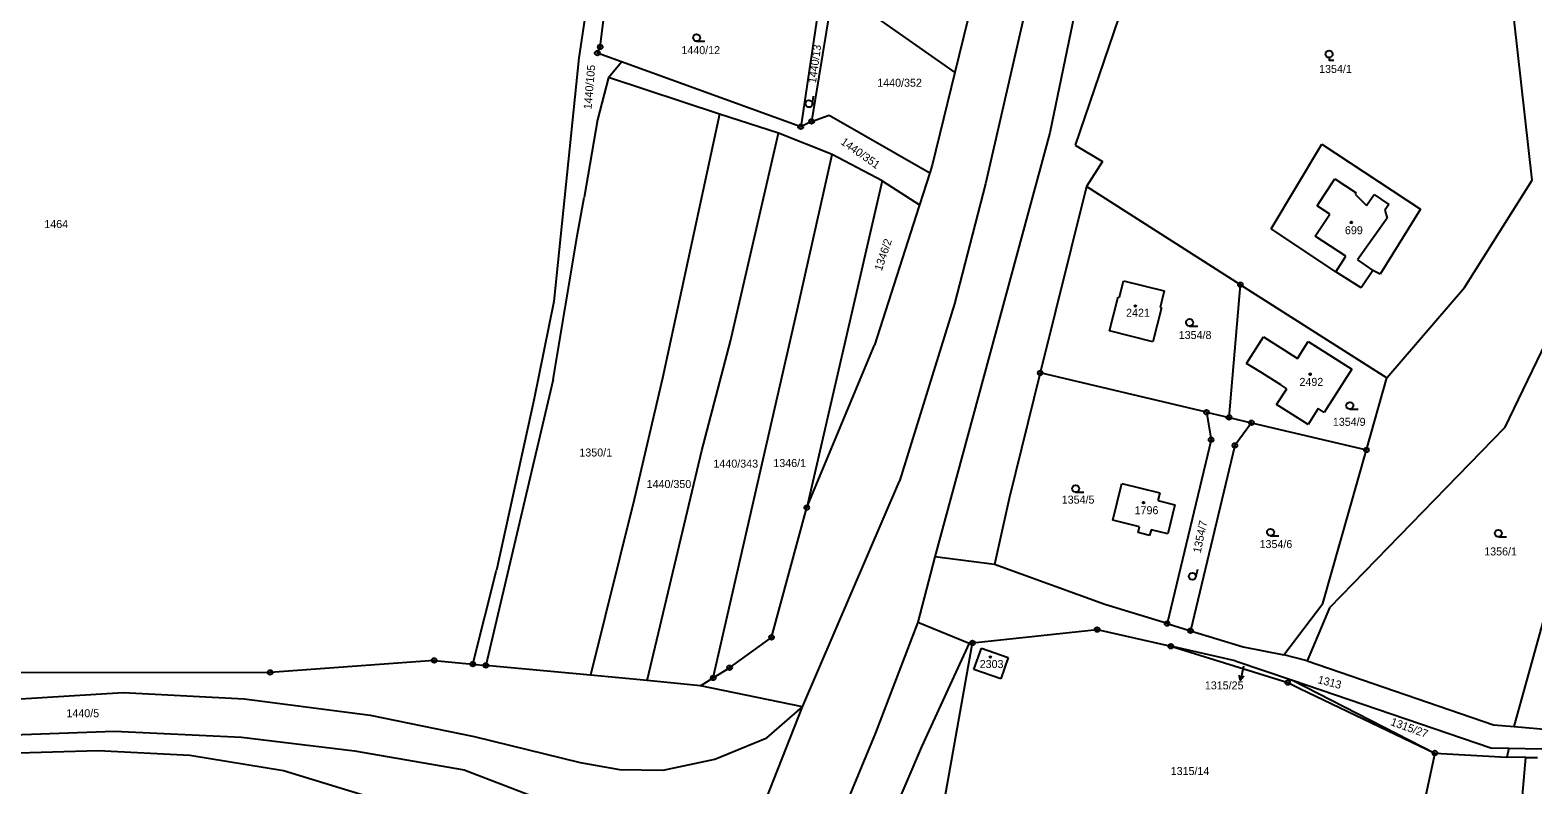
# Model space of a CAD drawing. Extents: x -779596 to -776743, y -1030330 to -1024513.
# Drawn here: x -778848.9 to -778529.6, y -1029527.2 to -1029366.8 of the extents above; entities that cross this region are included whole.
import ezdxf

# ---------------------------------------------------------------- set-up
doc = ezdxf.new("R2010")
doc.units = 0
for name, color, linetype in [('hranice parcel', 7, 'Continuous'), ('hranice vnitřní', 7, 'Continuous'), ('kultura', 7, 'Continuous'), ('Kód', 7, 'Continuous'), ('č_ parcel šipka', 7, 'Continuous'), ('č_pacel stav_', 7, 'Continuous'), ('č_parcel poz_', 7, 'Continuous')]:
    doc.layers.add(name, color=color, linetype=linetype)

msp = doc.modelspace()

# ---------------------------------------------------------------- linework, layer by layer
at = {"layer": 'hranice parcel'}
for points in [[(-778727.78, -1029370.36), (-778723.25, -1029334.33)], [(-778608.5, -1029337.19), (-778626.9, -1029391.19)], [(-778727.76, -1029341.91), (-778732.32, -1029372.68)], [(-778680.37, -1029354.91), (-778685.2, -1029387.32)], [(-778678.25, -1029357.68), (-778682.87, -1029386.19)], [(-778678.25, -1029357.68), (-778652.43, -1029375.78)], [(-778647.89, -1029357.22), (-778652.43, -1029375.78)], [(-778529.81, -1029398.69), (-778534.38, -1029357.58)], [(-778728.4, -1029371.67), (-778727.78, -1029370.36)], [(-778723.3, -1029373.52), (-778728.4, -1029371.67)], [(-778732.32, -1029372.68), (-778737.68, -1029424.44)], [(-778726, -1029376.83), (-778723.3, -1029373.52)], [(-778685.2, -1029387.32), (-778723.3, -1029373.52)], [(-778726, -1029376.83), (-778728.4, -1029385.86)], [(-778702.44, -1029384.63), (-778726, -1029376.83)], [(-778652.43, -1029375.78), (-778657.26, -1029395.5)], [(-778702.44, -1029384.63), (-778714.58, -1029440.73)], [(-778689.9, -1029388.68), (-778702.44, -1029384.63)], [(-778728.4, -1029385.86), (-778731.19, -1029402.33)], [(-778682.87, -1029386.19), (-778685.2, -1029387.32)], [(-778682.87, -1029386.19), (-778679.12, -1029384.87)], [(-778679.12, -1029384.87), (-778657.76, -1029397.08)], [(-778700.09, -1029432.9), (-778689.9, -1029388.68)], [(-778678.49, -1029393.24), (-778689.9, -1029388.68)], [(-778585.21, -1029409), (-778574.45, -1029391.04)], [(-778574.45, -1029391.04), (-778553.51, -1029404.79)], [(-778685.92, -1029426.38), (-778678.49, -1029393.24)], [(-778667.86, -1029398.83), (-778678.49, -1029393.24)], [(-778626.9, -1029391.19), (-778621.06, -1029394.71)], [(-778657.76, -1029397.08), (-778659.95, -1029403.89)], [(-778657.26, -1029395.5), (-778657.76, -1029397.08)], [(-778621.06, -1029394.71), (-778624.5, -1029400.03)], [(-778667.86, -1029398.83), (-778683.91, -1029468.24)], [(-778667.86, -1029398.83), (-778659.95, -1029403.89)], [(-778624.5, -1029400.03), (-778634.29, -1029439.63)], [(-778591.79, -1029420.88), (-778624.5, -1029400.03)], [(-778544.15, -1029421.45), (-778529.81, -1029398.69)], [(-778732.65, -1029410.17), (-778731.19, -1029402.33)], [(-778660.1, -1029404.35), (-778669.53, -1029433.74)], [(-778659.95, -1029403.89), (-778660.1, -1029404.35)], [(-778553.51, -1029404.79), (-778562.1, -1029418.66)], [(-778737.78, -1029441.03), (-778732.65, -1029410.17)], [(-778571.54, -1029418.12), (-778585.21, -1029409)], [(-778566.15, -1029421.57), (-778571.54, -1029418.12)], [(-778563.62, -1029417.83), (-778566.15, -1029421.57)], [(-778562.1, -1029418.66), (-778563.62, -1029417.83)], [(-778617.48, -1029423.49), (-778616.6, -1029420.02)], [(-778616.6, -1029420.02), (-778608.01, -1029422.19)], [(-778608.01, -1029422.19), (-778608.84, -1029425.71)], [(-778594.2, -1029449.09), (-778591.79, -1029420.88)], [(-778591.79, -1029420.88), (-778560.7, -1029440.69)], [(-778560.7, -1029440.69), (-778544.15, -1029421.45)], [(-778522.02, -1029422.99), (-778535.64, -1029451.32)], [(-778737.68, -1029424.44), (-778741.86, -1029445.38)], [(-778619.6, -1029430.67), (-778617.77, -1029423.42)], [(-778617.77, -1029423.42), (-778617.48, -1029423.49)], [(-778608.55, -1029425.78), (-778610.4, -1029433.04)], [(-778608.84, -1029425.71), (-778608.55, -1029425.78)], [(-778533.6, -1029514.77), (-778508.99, -1029425.9)], [(-778703.78, -1029504.41), (-778685.92, -1029426.38)], [(-778610.4, -1029433.04), (-778619.6, -1029430.67)], [(-778590.49, -1029437.61), (-778586.88, -1029431.96)], [(-778586.88, -1029431.96), (-778582.41, -1029434.8)], [(-778706.17, -1029456.11), (-778700.09, -1029432.9)], [(-778683.91, -1029468.24), (-778669.53, -1029433.74)], [(-778582.41, -1029434.8), (-778579.64, -1029436.54)], [(-778579.64, -1029436.54), (-778577.36, -1029432.91)], [(-778577.36, -1029432.91), (-778568.1, -1029438.8)], [(-778587.23, -1029439.59), (-778590.49, -1029437.61)], [(-778568.1, -1029438.8), (-778573.98, -1029448.01)], [(-778737.78, -1029441.03), (-778752.06, -1029501.76)], [(-778714.58, -1029440.73), (-778720.61, -1029466.53)], [(-778634.29, -1029439.63), (-778640.88, -1029466.3)], [(-778598.99, -1029447.96), (-778634.29, -1029439.63)], [(-778583.19, -1029442.17), (-778587.23, -1029439.59)], [(-778581.93, -1029442.97), (-778583.19, -1029442.17)], [(-778565.02, -1029455.97), (-778560.7, -1029440.69)], [(-778741.86, -1029445.38), (-778749.83, -1029481.55)], [(-778584.09, -1029446.36), (-778581.93, -1029442.97)], [(-778598.99, -1029447.96), (-778598.01, -1029453.83)], [(-778598.99, -1029447.96), (-778594.2, -1029449.09)], [(-778577.38, -1029450.6), (-778584.09, -1029446.36)], [(-778575.24, -1029447.18), (-778577.38, -1029450.6)], [(-778573.98, -1029448.01), (-778575.24, -1029447.18)], [(-778594.2, -1029449.09), (-778589.41, -1029450.22)], [(-778589.41, -1029450.22), (-778592.95, -1029455.03)], [(-778589.41, -1029450.22), (-778565.02, -1029455.97)], [(-778535.64, -1029451.32), (-778572.85, -1029489.52)], [(-778598.01, -1029453.83), (-778607.34, -1029492.88)], [(-778717.85, -1029505), (-778706.17, -1029456.11)], [(-778592.95, -1029455.03), (-778602.36, -1029494.4)], [(-778574.26, -1029488.64), (-778565.02, -1029455.97)], [(-778618.88, -1029470.91), (-778617, -1029463.13)], [(-778617, -1029463.13), (-778608.88, -1029465.13)], [(-778720.61, -1029466.53), (-778729.83, -1029503.87)], [(-778640.88, -1029466.3), (-778644, -1029480.3)], [(-778608.88, -1029465.13), (-778609.31, -1029466.73)], [(-778609.31, -1029466.73), (-778605.73, -1029467.68)], [(-778605.73, -1029467.68), (-778607.18, -1029473.82)], [(-778691.37, -1029495.81), (-778683.91, -1029468.24)], [(-778613.22, -1029472.31), (-778618.88, -1029470.91)], [(-778613.51, -1029473.51), (-778613.22, -1029472.31)], [(-778611.08, -1029474.13), (-778613.51, -1029473.51)], [(-778610.76, -1029472.94), (-778611.08, -1029474.13)], [(-778607.18, -1029473.82), (-778610.76, -1029472.94)], [(-778656.67, -1029478.73), (-778660.33, -1029492.59)], [(-778644, -1029480.3), (-778656.67, -1029478.73)], [(-778620.59, -1029488.85), (-778644, -1029480.3)], [(-778754.87, -1029501.49), (-778749.83, -1029481.55)], [(-778607.34, -1029492.88), (-778620.59, -1029488.85)], [(-778582.58, -1029499.53), (-778574.26, -1029488.64)], [(-778572.85, -1029489.52), (-778577.62, -1029500.78)], [(-778660.33, -1029492.59), (-778649.4, -1029497.07)], [(-778607.34, -1029492.88), (-778602.36, -1029494.4)], [(-778700.29, -1029502.26), (-778691.37, -1029495.81)], [(-778648.72, -1029497), (-778622.23, -1029494.14)], [(-778622.23, -1029494.14), (-778606.57, -1029497.68)], [(-778602.36, -1029494.4), (-778591.21, -1029497.79)], [(-778649.4, -1029497.07), (-778659.51, -1029519.08)], [(-778654.86, -1029531.63), (-778648.72, -1029497)], [(-778648.72, -1029497), (-778649.4, -1029497.07)], [(-778648.41, -1029502.61), (-778646.81, -1029498.09)], [(-778646.81, -1029498.09), (-778641.11, -1029500.11)], [(-778606.57, -1029497.68), (-778581.73, -1029505.42)], [(-778592.91, -1029500.77), (-778606.57, -1029497.68)], [(-778591.21, -1029497.79), (-778582.58, -1029499.53)], [(-778577.62, -1029500.78), (-778582.58, -1029499.53)], [(-778763.07, -1029500.72), (-778797.93, -1029503.27)], [(-778763.07, -1029500.72), (-778754.87, -1029501.49)], [(-778754.87, -1029501.49), (-778752.06, -1029501.76)], [(-778729.83, -1029503.87), (-778752.06, -1029501.76)], [(-778703.78, -1029504.41), (-778700.29, -1029502.26)], [(-778642.7, -1029504.65), (-778648.41, -1029502.61)], [(-778641.11, -1029500.11), (-778642.7, -1029504.65)], [(-778592.91, -1029500.77), (-778580.71, -1029504.93)], [(-778577.62, -1029500.78), (-778537.99, -1029514.4)], [(-778797.93, -1029503.27), (-778855.38, -1029503.38)], [(-778717.85, -1029505), (-778729.83, -1029503.87)], [(-778706.49, -1029506.08), (-778717.85, -1029505)], [(-778706.49, -1029506.08), (-778703.78, -1029504.41)], [(-778581.73, -1029505.42), (-778579.17, -1029506.65)], [(-778580.71, -1029504.93), (-778550.46, -1029520.38)], [(-778580.71, -1029504.93), (-778538.55, -1029519.29)], [(-778684.79, -1029510.56), (-778706.49, -1029506.08)], [(-778579.17, -1029506.65), (-778550.46, -1029520.38)], [(-778696.97, -1029541.5), (-778684.79, -1029510.56)], [(-778537.99, -1029514.4), (-778533.6, -1029514.77)], [(-778533.6, -1029514.77), (-778521.55, -1029515.8)], [(-778853.89, -1029520.43), (-778834.43, -1029519.83)], [(-778834.43, -1029519.83), (-778814.96, -1029520.83)], [(-778814.96, -1029520.83), (-778795.06, -1029524.1)], [(-778659.51, -1029519.08), (-778665.97, -1029534.12)], [(-778550.46, -1029520.38), (-778558.11, -1029555.83)], [(-778550.46, -1029520.38), (-778535.14, -1029521.29)], [(-778549.1, -1029687.49), (-778546.18, -1029658.23), (-778543.17, -1029626.98), (-778537.34, -1029583.98), (-778533.31, -1029546.53), (-778531.17, -1029521.31)], [(-778538.55, -1029519.29), (-778534.74, -1029519.37)], [(-778534.74, -1029519.37), (-778535.14, -1029521.29)], [(-778531.17, -1029521.31), (-778535.14, -1029521.29)], [(-778534.74, -1029519.37), (-778510.24, -1029519.88)], [(-778531.17, -1029521.31), (-778528.68, -1029521.33)], [(-778795.06, -1029524.1), (-778774.48, -1029530.4)]]:
    msp.add_lwpolyline(points, dxfattribs=at)
at = {"layer": 'hranice vnitřní'}
for points in [[(-778635.87, -1029355.53), (-778645.93, -1029399.47)], [(-778625.82, -1029357.43), (-778632.3, -1029388.6)], [(-778632.3, -1029388.6), (-778656.67, -1029478.73)], [(-778645.93, -1029399.47), (-778652.55, -1029424.96)], [(-778573.93, -1029401.71), (-778571.73, -1029398.38)], [(-778571.73, -1029398.38), (-778567.19, -1029401.38)], [(-778575.5, -1029404.09), (-778573.93, -1029401.71)], [(-778567.19, -1029401.38), (-778567.38, -1029401.67)], [(-778567.38, -1029401.67), (-778564.99, -1029404.04)], [(-778564.99, -1029404.04), (-778564.18, -1029402.88)], [(-778564.18, -1029402.88), (-778563.34, -1029401.68)], [(-778563.34, -1029401.68), (-778560.26, -1029403.82)], [(-778560.26, -1029403.82), (-778561.09, -1029405.02)], [(-778575.87, -1029410.54), (-778572.79, -1029405.87)], [(-778572.79, -1029405.87), (-778575.5, -1029404.09)], [(-778560.63, -1029406.76), (-778566.91, -1029415.61)], [(-778561.09, -1029405.02), (-778560.63, -1029406.76)], [(-778569.37, -1029414.83), (-778575.87, -1029410.54)], [(-778571.54, -1029418.12), (-778569.37, -1029414.83)], [(-778566.91, -1029415.61), (-778563.62, -1029417.83)], [(-778652.55, -1029424.96), (-778664.2, -1029462.63)], [(-778684.79, -1029510.56), (-778664.2, -1029462.63)], [(-778660.33, -1029492.59), (-778669.3, -1029516.12)], [(-778852.12, -1029508.97), (-778829.17, -1029507.5)], [(-778829.17, -1029507.5), (-778803.45, -1029508.85)], [(-778803.45, -1029508.85), (-778776.65, -1029512.33)], [(-778776.65, -1029512.33), (-778754.58, -1029516.89)], [(-778692.4, -1029517.13), (-778684.79, -1029510.56)], [(-778854.48, -1029516.62), (-778830.99, -1029515.75)], [(-778830.99, -1029515.75), (-778804.01, -1029516.98)], [(-778804.01, -1029516.98), (-778779.97, -1029519.95)], [(-778754.58, -1029516.89), (-778732.02, -1029522.38)], [(-778703.44, -1029521.71), (-778692.4, -1029517.13)], [(-778669.3, -1029516.12), (-778694.21, -1029576.29)], [(-778779.97, -1029519.95), (-778756.7, -1029523.97)], [(-778714.4, -1029524.05), (-778703.44, -1029521.71)], [(-778756.7, -1029523.97), (-778727.92, -1029535.02)], [(-778732.02, -1029522.38), (-778723.71, -1029523.85)], [(-778723.71, -1029523.85), (-778714.4, -1029524.05)]]:
    msp.add_lwpolyline(points, dxfattribs=at)
at = {"layer": 'kultura'}
for points in [[(-778707.31, -1029369.16), (-778705.56, -1029369.16)], [(-778572.93, -1029372.63), (-778572.93, -1029373.13), (-778571.907, -1029373.13)], [(-778682.7, -1029382.53), (-778682.46, -1029380.797)], [(-778602.58, -1029429.66), (-778600.83, -1029429.66)], [(-778568.54, -1029447.31), (-778566.79, -1029447.31)], [(-778626.78, -1029464.95), (-778625.03, -1029464.95)], [(-778585.37, -1029474.23), (-778583.62, -1029474.23)], [(-778536.98, -1029474.45), (-778535.23, -1029474.45)], [(-778601.26, -1029483.01), (-778600.852, -1029481.309)]]:
    msp.add_lwpolyline(points, dxfattribs=at)
for centre, radius in [((-778707.31, -1029368.41), 0.75), ((-778572.93, -1029371.88), 0.75), ((-778683.442, -1029382.427), 0.749), ((-778568.22, -1029407.65), 0.175), ((-778614.12, -1029425.4), 0.175), ((-778602.58, -1029428.91), 0.75), ((-778576.96, -1029439.89), 0.175), ((-778568.54, -1029446.56), 0.75), ((-778626.78, -1029464.2), 0.75), ((-778612.35, -1029467.18), 0.175), ((-778585.37, -1029473.48), 0.75), ((-778536.98, -1029473.7), 0.75), ((-778601.989, -1029482.835), 0.75), ((-778644.9, -1029499.99), 0.175)]:
    msp.add_circle(centre, radius, dxfattribs=at)
at = {"layer": 'Kód'}
for centre, radius in [((-778728.4, -1029371.67), 0.5), ((-778728.4, -1029371.67), 0.032), ((-778727.78, -1029370.36), 0.5), ((-778727.78, -1029370.36), 0.032), ((-778685.2, -1029387.32), 0.5), ((-778685.2, -1029387.32), 0.032), ((-778682.87, -1029386.19), 0.5), ((-778682.87, -1029386.19), 0.032), ((-778591.79, -1029420.88), 0.5), ((-778591.79, -1029420.88), 0.032), ((-778634.29, -1029439.63), 0.5), ((-778634.29, -1029439.63), 0.032), ((-778598.99, -1029447.96), 0.5), ((-778598.99, -1029447.96), 0.032), ((-778594.2, -1029449.09), 0.5), ((-778594.2, -1029449.09), 0.032), ((-778589.41, -1029450.22), 0.5), ((-778589.41, -1029450.22), 0.032), ((-778598.01, -1029453.83), 0.5), ((-778598.01, -1029453.83), 0.032), ((-778592.95, -1029455.03), 0.5), ((-778592.95, -1029455.03), 0.032), ((-778565.02, -1029455.97), 0.5), ((-778565.02, -1029455.97), 0.032), ((-778683.91, -1029468.24), 0.5), ((-778683.91, -1029468.24), 0.032), ((-778607.34, -1029492.88), 0.5), ((-778607.34, -1029492.88), 0.032), ((-778691.37, -1029495.81), 0.5), ((-778691.37, -1029495.81), 0.032), ((-778622.23, -1029494.14), 0.5), ((-778622.23, -1029494.14), 0.032), ((-778602.36, -1029494.4), 0.5), ((-778602.36, -1029494.4), 0.032), ((-778648.72, -1029497), 0.5), ((-778648.72, -1029497), 0.032), ((-778606.57, -1029497.68), 0.5), ((-778606.57, -1029497.68), 0.032), ((-778797.93, -1029503.27), 0.5), ((-778763.07, -1029500.72), 0.5), ((-778763.07, -1029500.72), 0.032), ((-778754.87, -1029501.49), 0.5), ((-778754.87, -1029501.49), 0.032), ((-778752.06, -1029501.76), 0.5), ((-778752.06, -1029501.76), 0.032), ((-778700.29, -1029502.26), 0.5), ((-778700.29, -1029502.26), 0.032), ((-778797.93, -1029503.27), 0.032), ((-778703.78, -1029504.41), 0.5), ((-778703.78, -1029504.41), 0.032), ((-778581.73, -1029505.42), 0.5), ((-778581.73, -1029505.42), 0.032), ((-778550.46, -1029520.38), 0.5), ((-778550.46, -1029520.38), 0.032)]:
    msp.add_circle(centre, radius, dxfattribs=at)
at = {"layer": 'č_ parcel šipka'}
for points in [[(-778591.12, -1029501.97), (-778591.753, -1029504.902)], [(-778591.11, -1029501.92), (-778591.12, -1029501.97)], [(-778591.054, -1029504.03), (-778591.753, -1029504.902), (-778592.031, -1029503.819)]]:
    msp.add_lwpolyline(points, dxfattribs=at)

# ---------------------------------------------------------------- texts
msp.add_text('1315/25', height=1.7, dxfattribs=at).set_placement((-778599.333, -1029506.86))
at = {"layer": 'č_pacel stav_'}
for s, p in [('699', (-778569.57, -1029410.15)), ('2421', (-778616.07, -1029427.69)), ('2492', (-778579.23, -1029442.37)), ('1796', (-778614.26, -1029469.64)), ('2303', (-778647.17, -1029502.33))]:
    msp.add_text(s, height=1.7, dxfattribs=at).set_placement(p)
at = {"layer": 'č_parcel poz_'}
for s, height, p in [('1440/12', 1.7, (-778710.54, -1029371.88)), ('1354/1', 1.7, (-778575.06, -1029375.88)), ('1440/352', 1.7, (-778668.93, -1029378.81)), ('1464', 1.7, (-778845.9, -1029408.84)), ('1354/8', 1.7, (-778604.88, -1029432.41)), ('1354/9', 1.7, (-778572.14, -1029450.86)), ('1350/1', 1.7, (-778732.22, -1029457.38)), ('1440/343', 1.7, (-778703.73, -1029459.74)), ('1346/1', 1.7, (-778691.01, -1029459.62)), ('1440/350', 1.7, (-778717.93, -1029464.07)), ('1354/5', 1.7, (-778629.74, -1029467.39)), ('1354/6', 1.7, (-778587.71, -1029476.84)), ('1356/1', 1.7, (-778539.98, -1029478.4)), ('1315/25', 0.1, (-778591.143, -1029501.72)), ('1440/5', 1.7, (-778841.2, -1029512.78)), ('1315/14', 1.7, (-778606.59, -1029525.06))]:
    msp.add_text(s, height=height, dxfattribs=at).set_placement(p)
for s, rotation, p in [('1440/13', 81.90065, (-778681.969, -1029378.144)), ('1440/105', 85.10068, (-778729.639, -1029383.669)), ('1440/351', 324.70258, (-778676.852, -1029390.873)), ('1346/2', 71.60057, (-778667.976, -1029418.058)), ('1354/7', 78.20062, (-778600.224, -1029477.994)), ('1313', 345.50275, (-778575.477, -1029505.527)), ('1315/27', 340.10271, (-778560.014, -1029514.411))]:
    msp.add_text(s, height=1.7, rotation=rotation, dxfattribs=at).set_placement(p)

doc.saveas('drawing.dxf')
